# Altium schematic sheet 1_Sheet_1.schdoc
size 302 x 215 mm; Name: A_A4; Symbol: A_A4; Device: A_A4; @Project Name: Sheet_1; REV: 1.0; Date: 2025-08-08; Sheet: 1/1; Draw By: nitishsharma; Company: Your Company; Convert to PCB: yes; Add into BOM: yes; spicePre: .
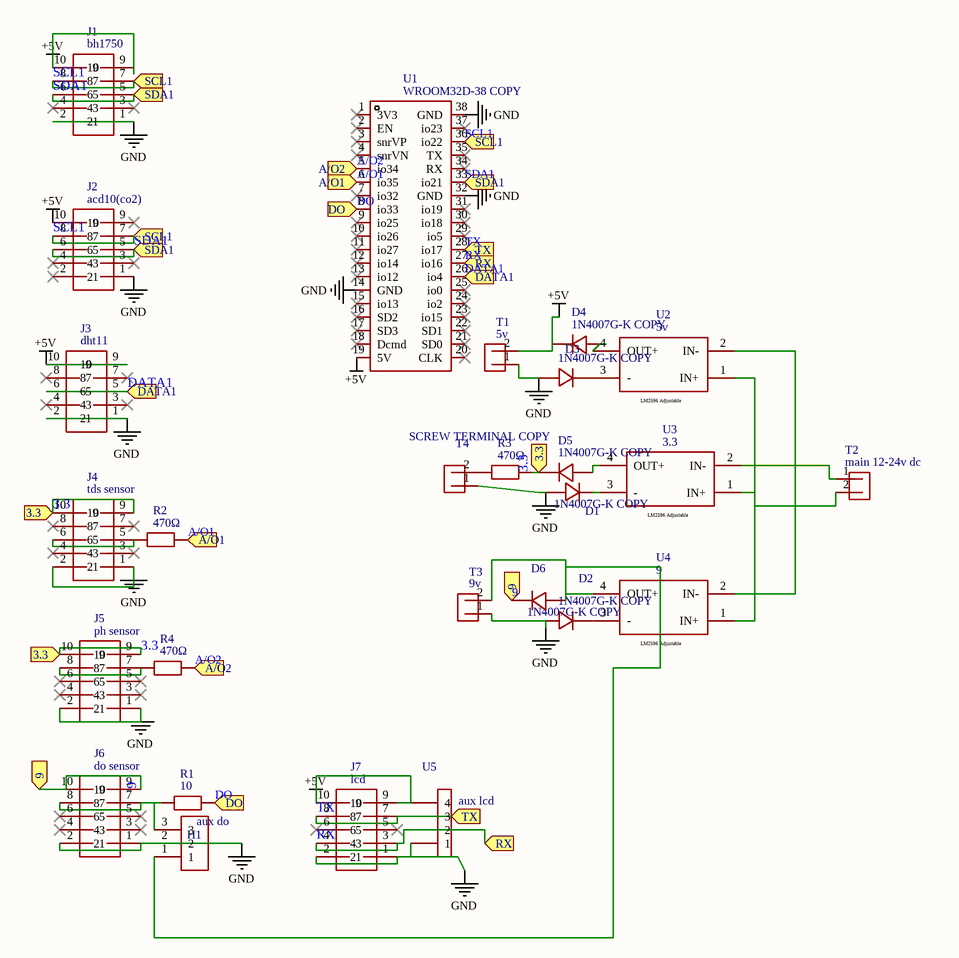
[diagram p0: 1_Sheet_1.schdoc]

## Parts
D1  1N4007G-K COPY  [DO-204AL_BD2.4-L4.7-P8.70-D1.1-RD]
D2  1N4007G-K COPY  [DO-204AL_BD2.4-L4.7-P8.70-D1.1-RD]
D3  1N4007G-K COPY  [DO-204AL_BD2.4-L4.7-P8.70-D1.1-RD]
D4  1N4007G-K COPY  [DO-204AL_BD2.4-L4.7-P8.70-D1.1-RD]
D5  1N4007G-K COPY  [DO-204AL_BD2.4-L4.7-P8.70-D1.1-RD]
D6  1N4007G-K COPY  [DO-204AL_BD2.4-L4.7-P8.70-D1.1-RD]
H1  aux do  [HEADER3X1]
J1  bh1750  [FRC10]
J2  acd10(co2)  [FRC10]
J3  dht11  [FRC10]
J4  tds sensor  [FRC10]
J5  ph sensor  [FRC10]
J6  do sensor  [FRC10]
J7  lcd  [FRC10]
R1  10  [RES-TH_BD2.4-L6.4-P11.12-D0.6]
R2  470Ω  [RES-TH_BD2.4-L6.4-P11.12-D0.6]
R3  470Ω  [RES-TH_BD2.4-L6.4-P11.12-D0.6]
R4  470Ω  [RES-TH_BD2.4-L6.4-P11.12-D0.6]
T1  5v  [M02 SCREW TERMINAL 5MM 10X8MM]
T2  main 12-24v dc  [M02 SCREW TERMINAL 5MM 10X8MM]
T3  9v  [M02 SCREW TERMINAL 5MM 10X8MM]
T4  SCREW TERMINAL COPY  [M02 SCREW TERMINAL 5MM 10X8MM]
U1  WROOM32D-38 COPY  [WROOM32D]
U2  5v  [LM2596:YAAJ_DCDC_STEPDOWN_LM2596]
U3  3.3  [LM2596:YAAJ_DCDC_STEPDOWN_LM2596]
U4  9  [LM2596:YAAJ_DCDC_STEPDOWN_LM2596]
U5  aux lcd  [HEADER4]

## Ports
3.3 (in), 9 (in), A/O1 (in), A/O2 (in), DATA1 (in), DO (in), RX (in), SCL1 (in), SDA1 (in), TX (in)

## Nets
+5V: D4.1(C) J1.9 J1.10 J2.10 J3.9 J3.10 J7.9 J7.10 T1.2 U1.19(5V) U5.4
GND: D1.2(A) D2.2(A) D3.2(A) H1.2 J1.1 J1.2 J2.1 J3.1 J3.2 J4.1 J4.2 J5.1 J5.2 J6.1 J6.2 J7.1 J7.2 T1.1 T3.1 T4.1 U1.14(GND) U1.32(GND) U1.38(GND) U5.1
3.3: D5.1(C) J4.9 J4.10 J5.9 J5.10 R3.2 ; port 3.3
9: D6.1(C) J6.9 J6.10 ; port 9
A/O1: R2.2 U1.6(io35) ; port A/O1
A/O2: R4.2 U1.5(io34) ; port A/O2
DATA1: J3.5 J3.6 U1.26(io4) ; port DATA1
DO: R1.2 U1.8(io33) ; port DO
RX: J7.3 J7.4 U1.27(io16) U5.2 ; port RX
SCL1: J1.7 J1.8 J2.7 J2.8 U1.36(io22) ; port SCL1
SDA1: J1.5 J1.6 J2.5 J2.6 U1.33(io21) ; port SDA1
TX: J7.7 J7.8 U1.28(io17) U5.3 ; port TX
NetD1_1: D1.1(C) U3.3(-)
NetD2_1: D2.1(C) U4.3(-)
NetD3_1: D3.1(C) U2.3(-)
NetD4_2: D4.2(A) U2.4(OUT+)
NetD5_2: D5.2(A) U3.4(OUT+)
NetD6_2: D6.2(A) H1.1 T3.2 U4.4(OUT+)
NetH1_3: H1.3 J6.7 J6.8 R1.1
NetJ4_5: J4.5 J4.6 R2.1
NetJ5_7: J5.7 J5.8 R4.1
NetR3_1: R3.1 T4.2
NetT2_1: T2.1 U2.2(IN-) U3.2(IN-) U4.2(IN-)
NetT2_2: T2.2 U2.1(IN+) U3.1(IN+) U4.1(IN+)

Not connected (* = marked no-connect by the designer): J1 3* 4*; J2 2* 3* 4* 9*; J3 3* 4* 7* 8*; J4 3* 4* 7* 8*; J5 3* 4* 5* 6*; J6 3* 4* 5* 6*; J7 5* 6*; U1 1(3V3)* 2(EN)* 3(snrVP)* 4(snrVN)* 7(io32)* 9(io25)* 10(io26)* 11(io27)* 12(io14)* 13(io12)* 15(io13)* 16(SD2)* 17(SD3)* 18(Dcmd)* 20(CLK)* 21(SD0)* 22(SD1)* 23(io15)* 24(io2)* 25(io0)* 29(io5)* 30(io18)* 31(io19)* 34(RX)* 35(TX)* 37(io23)*

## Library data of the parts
D1-D6 = 1N4007G-K COPY: Manufacturer: Taiwan Semiconductor(台湾半导体); Convert to PCB: yes; Contributor: LCSC
H1 = aux do: Convert to PCB: yes; Contributor: elfred
J1 = bh1750: Convert to PCB: yes; Contributor: amit071089
J2 = acd10(co2): Convert to PCB: yes; Contributor: amit071089
J3 = dht11: Convert to PCB: yes; Contributor: amit071089
J4 = tds sensor: Convert to PCB: yes; Contributor: amit071089
J5 = ph sensor: Convert to PCB: yes; Contributor: amit071089
J6 = do sensor: Convert to PCB: yes; Contributor: amit071089
J7 = lcd: Convert to PCB: yes; Contributor: amit071089
R1 = 10: Manufacturer: Tyohm(幸亚电阻); Manufacturer Part: RD1/4W470RJT26; Convert to PCB: yes; nameAlias: Value; Contributor: lcsc
R2-R4 = 470Ω: Manufacturer: Tyohm(幸亚电阻); Manufacturer Part: RD1/4W470RJT26; Convert to PCB: yes; nameAlias: Value; Contributor: lcsc
T1 = 5v: Convert to PCB: yes; Contributor: serioga.com
T2 = main 12-24v dc: Convert to PCB: yes; Contributor: serioga.com
T3 = 9v: Convert to PCB: yes; Contributor: serioga.com
T4 = SCREW TERMINAL COPY: Convert to PCB: yes; Contributor: serioga.com
U1 = WROOM32D-38 COPY: Convert to PCB: yes; Contributor: allanmok
U2 = 5v: Add into BOM: yes; Origin Footprint: YAAJ_DCDC_StepDown_LM2596; Contributor: ee22b001
U3 = 3.3: Add into BOM: yes; Origin Footprint: YAAJ_DCDC_StepDown_LM2596; Contributor: ee22b001
U4 = 9: Add into BOM: yes; Origin Footprint: YAAJ_DCDC_StepDown_LM2596; Contributor: ee22b001
U5 = aux lcd: Manufacturer: unknow; Convert to PCB: yes; Contributor: otebono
